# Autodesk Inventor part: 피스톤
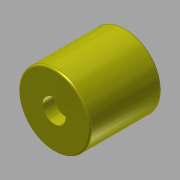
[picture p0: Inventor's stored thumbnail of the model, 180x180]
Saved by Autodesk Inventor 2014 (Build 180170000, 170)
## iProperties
Created: 2018-01
Part Number: 피스톤
Material: 강철, 탄소
Document SubType Name: Modeling
Designer: mduedu
Density: 7.87 g/cm^3
Appearance: 노란색
Mass: 44.9853 g
Surface Area: 21.9333 cm^2
Volume: 5.71605 cm^3
Author: mduedu
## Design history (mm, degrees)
sketch "스케치1"
  geometry: C1 r 10 at (0, 0); 1 further point
  constraints: 1 centre point, 1 coincident
  dimensions: "d0" = 20 diameter of C1
extrude "돌출1" new body sketch "스케치1" distance "d1" = 20; taper "d2" = 0 deg
hole "구멍1" diameter "d5" = 7; stored, may be unused: countersink angle "d9" = 90 deg, drill point angle "d11" = 0 deg; dims "d6" = 6, "d7" = 4, "d8" = 2, "d10" = 10, "d12" = 10, "d13" = 10
chamfer "모따기1" distance "d14" = 0.5; stored, may be unused: second distance "d15" = 2, angle "d16" = 45 deg
fillet "모깎기1" dims "d17" = 0.5
sketch "스케치2"
  geometry: 2 further points
  constraints: 1 coincident
sketch "스케치3"
  geometry: 2 further points
  constraints: 1 coincident
hole "구멍2" sketch "스케치3" at (0, 0) diameter "d18" = 3.4; stored, may be unused: countersink angle "d22" = 90 deg, drill point angle "d24" = 0 deg; dims "d19" = 6, "d20" = 6.5, "d21" = 3.4, "d23" = 8
node "솔리드1"
